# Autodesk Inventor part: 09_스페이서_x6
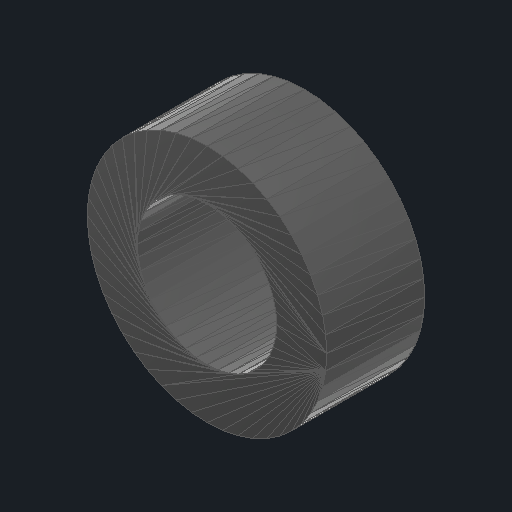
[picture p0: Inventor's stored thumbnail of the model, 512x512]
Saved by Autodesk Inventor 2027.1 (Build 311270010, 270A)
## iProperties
Created: 2026-11
Part Number: 09_스페이서_x6
Material: 일반
Document SubType Name: Modeling
Designer: djshs
Density: 1 g/cm^3
Appearance: 기본값
Author: djshs
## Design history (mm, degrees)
node "09_스페이서_x6"
  node "MeshFeature1"
